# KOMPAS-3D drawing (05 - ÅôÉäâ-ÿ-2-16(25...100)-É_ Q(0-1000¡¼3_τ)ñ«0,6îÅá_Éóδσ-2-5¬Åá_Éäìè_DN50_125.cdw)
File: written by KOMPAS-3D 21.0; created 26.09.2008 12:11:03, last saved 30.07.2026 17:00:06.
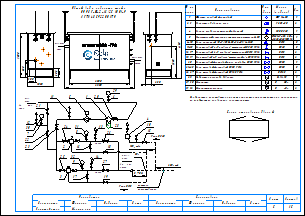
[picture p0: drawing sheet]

Sheets 1-2: A3, landscape

Document properties: Наименование: Макро:21; Автор: RaskoAdmin; Форматы листов документа: 2xA3; Полное имя файла: \\UR38nt01\Departments\КТО\КБ ПУРДГ\Заявки\Прайс-лист на типовые шкафы ГРПШ\ПУРДГ_стандарт_30_04_2026\ПУРДГ с РДНК\ПУРДГ-Ш-2-16(25...100)-Р_ Q(0-1000нм3_ч)до0,6МПа_Рвых-2-5кПа_РДНК_DN50_125.cdw

Title block, sheet 1: Наименование: Пункт учета газа / ПУГ-Ш-400-Р / ЛГТИ.485922.001ТУ; designation: ЛГТИ.03.4411141; sheet number: 1; Количество листов документа: 2; organisation: ООО "ЭЛЬСТЕР Газэлектроника"; Форматы листов документа: A3; stored path: C:\Рабочие документы\Компас\ПУГ\Схема.cdw; Разработал: Устинов; Проверил: Кошкин; Утвердил: Кошкин
Title block, sheet 2: sheet number: 2; stored path: D:\Рабочие документы\Заявки\ПУРДГ\ПУРДГ-ШУЭО-2-100-Р 4411220.cdw; designation, second copy: ЛГТИ.03.4411141-

Views: Вид 1, Вид 2
Referenced files: wcvoit.frw
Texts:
  Normal
  № на
  схеме
  Усл.
  обозн.
  Марка
  (модель)
  Кол.
  Фильтр газовый фланцевый
  ФГ 16-50
  Регулятор давления газа
  РДНК-50
  Клапан предохранительный сбросной
  КПС DN20
  Измерительный комплекс с ротационным счетчиком Ду50
  СГ-ЭК-Р-(0,2...2,0)-
  Кран кнопочный VE-РАСКО-НЗ-1,6-G1/2-М20
  DN15
  Кран шаровой "под приварку" штуцерный DN20 PN16
  DN20
  Кран шаровой "под приварку" штуцерный DN15 PN16
  Кран шаровой "под приварку" штуцерный п/п DN15 PN16
  Кран шаровой фланцевый с мех. приводом DN50 PN16
  Кран шаровой фланцевый DN50 PN16
  Кран шаровой фланцевый DN125 PN16
  DN50
  DN125
  Индикатор перепада давления
  Манометр
  Манометр-напоромер
  Delta 15
  0...     МПа
  0...     кПа
  Общий вид и габариты шкафа
  ПУРДГ-Ш-2-16(25...100)-Р
  Выход газа
  Вход газа
  logo-rasko-ge.png
  DN 1
  местное
  сопротивление
  Римп DN15
  Римп DN20
  Выход
  газа
  Р=     кПа
  Вход
  Р=       МПа
  PDI
  Схема открывания дверей
  Предприятие изготовитель может заменять комплектующие на аналогичные,
  не ухудшающие заявленных характеристик.
  Должность
  Конструктор
  Фамилия
  Подпись
  Дата
  Согласовано
  Максимкин
  Лист
  Листов
  POLYLINE_STYLE_0.18_RGB_0_0_0
  POLYLINE_STYLE_0.50_RGB_0_0_0
  POLYLINE_STYLE_0.34_RGB_0_0_0
  PHANTOM_RGB_0_0_0_SC_1_THICK_0.18
  K5LT_THIN_RGB_0_0_0_THICK_0.18
  K5LT32769_RGB_0_0_0_THICK_0.18
  K5LT12_RGB_0_0_0_SC_1_THICK_0.18
  K5LT_DASHED_RGB_0_0_0_SC_1_THICK_0.18
  ACISOTGL_RGB_0_0_0_SC_0.8_THICK_0.25
  CONTINUOUS_RGB_0_127_31_THICK_0.3
  CONTINUOUS_RGB_0_0_255_THICK_0.35
  CONTINUOUS_RGB_255_0_0_THICK_0.35
  POLYLINE_STYLE_0.25_RGB_0_0_0
  CONTINUOUS_RGB_0_0_0_THICK_0.5
  POLYLINE_STYLE_0.35_RGB_0_0_255
  CONTINUOUS_RGB_0_0_0_THICK_0.4
  CONTINUOUS_RGB_0_0_0_THICK_0.35
  НЕВИДИМАЯ_RGB_0_0_0_SC_0.3_THICK_0.25
  СONTINUOUS_RGB_0_0_0_THICK_0.25
  ОСЕВАЯ2_RGB_248_153_30_SC_0.3_THICK_0.25
  Без оформления
Dimensions and other numbers on the sheet: 1; 2, 3; 2; 4; 5; 6-10; 11-15; 16, 17; 18, 19; 20; 21-25; 26, 27; 28; 29, 30; 31, 32; 1500; 250; 300; 1050; 550; 305; 2500; 4130; 2000; 2800; 5,,,7DN 1; 7; 30; 12; 21; 22; 23; 11; 6; 29; 24; 31; 8; 16; 13; 26; 18; 10; 15; 25; 32; 9; 3; 17; 14; 27; 19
